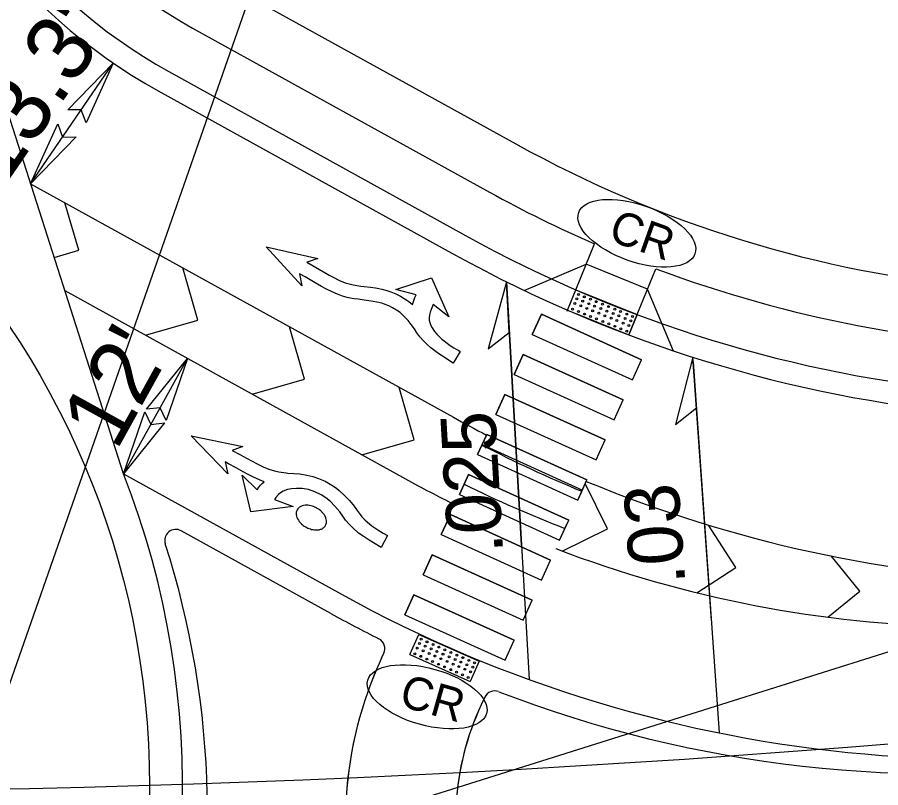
# Model space of a CAD drawing. Extents: x 2010838 to 2015151, y 441905 to 447792.
# Drawn here: x 2013251.3 to 2013329.7, y 444918.3 to 444988.3 of the extents above; entities that cross this region are included whole.
import ezdxf

# ---------------------------------------------------------------- set-up
doc = ezdxf.new("R2010")
doc.units = 0
for name, color, linetype in [('A-Wall-Abov', 7, 'Continuous'), ('A-Wall-Blow', 7, 'Continuous'), ('A-Wall-Comp', 7, 'Continuous'), ('C-Alignment Geometry', 7, 'Continuous'), ('C-CURB STOPS', 7, 'Continuous'), ('C-Grave Plots', 7, 'Continuous'), ('CLRD', 7, 'Continuous'), ('Default_10ft_LIDAR_Contou', 7, 'Continuous'), ('HATCH', 7, 'Continuous'), ('s-Existing Major', 7, 'Continuous'), ('S-Existing Minor', 7, 'Continuous'), ('S-overhead electric', 7, 'Continuous'), ('TEXT-LG', 7, 'Continuous'), ('TEXT-MED', 7, 'Continuous'), ('X4', 7, 'Continuous')]:
    doc.layers.add(name, color=color, linetype=linetype)

msp = doc.modelspace()

# ---------------------------------------------------------------- linework, layer by layer
at = {"layer": 'A-Wall-Abov'}
for points in [[(2013273.893, 444967.437), (2013278.566, 444966.374), (2013277.623, 444966.045), (2013277.588, 444966.033), (2013278.734, 444965.365), (2013279.321, 444965.031), (2013279.597, 444964.879), (2013280.083, 444964.616), (2013280.368, 444964.467), (2013280.557, 444964.377), (2013281.071, 444964.172), (2013281.419, 444964.066), (2013281.682, 444964.001), (2013281.973, 444963.944), (2013282.294, 444963.892), (2013282.492, 444963.866), (2013282.793, 444963.829), (2013283.38, 444963.785), (2013283.807, 444963.723), (2013284.116, 444963.664), (2013284.412, 444963.594), (2013284.847, 444963.47), (2013285.217, 444963.342), (2013285.656, 444963.16), (2013286.087, 444962.942), (2013286.426, 444962.741), (2013286.666, 444962.581), (2013286.839, 444962.455), (2013287.174, 444962.184), (2013287.232, 444962.371), (2013287.332, 444962.646), (2013287.402, 444962.819), (2013287.525, 444963.086), (2013285.656, 444963.558), (2013288.921, 444964.632), (2013290.493, 444961.071), (2013289.067, 444962.206), (2013288.989, 444962.041), (2013288.87, 444961.752), (2013288.78, 444961.488), (2013288.726, 444961.247), (2013288.704, 444960.992), (2013288.711, 444960.783), (2013288.784, 444960.461), (2013288.846, 444960.289), (2013288.963, 444960.068), (2013289.174, 444959.733), (2013289.393, 444959.5), (2013289.645, 444959.253), (2013289.862, 444959.057), (2013290.072, 444958.879), (2013290.327, 444958.679), (2013290.498, 444958.554), (2013290.694, 444958.418), (2013290.938, 444958.261), (2013291.142, 444958.138), (2013291.386, 444958.002), (2013291.505, 444957.939), (2013290.888, 444956.878), (2013290.45, 444957.146), (2013290.049, 444957.404), (2013289.684, 444957.649), (2013289.335, 444957.893), (2013289.104, 444958.062), (2013288.843, 444958.269), (2013288.518, 444958.557), (2013288.174, 444958.903), (2013287.859, 444959.266), (2013287.592, 444959.636), (2013287.356, 444959.996), (2013287.073, 444960.382), (2013286.777, 444960.741), (2013286.366, 444961.178), (2013286.061, 444961.461), (2013285.74, 444961.686), (2013285.365, 444961.908), (2013285.028, 444962.074), (2013284.707, 444962.206), (2013284.476, 444962.281), (2013284.112, 444962.366), (2013283.433, 444962.502), (2013282.804, 444962.603), (2013282.239, 444962.674), (2013281.887, 444962.712), (2013281.704, 444962.738), (2013281.241, 444962.832), (2013280.826, 444962.951), (2013280.356, 444963.127), (2013279.873, 444963.343), (2013279.37, 444963.593), (2013278.927, 444963.838), (2013278.345, 444964.174), (2013277.423, 444964.709), (2013276.928, 444964.99), (2013277.128, 444963.901)], [(2013267.078, 444950.245), (2013271.776, 444949.299), (2013270.807, 444948.934), (2013271.482, 444948.563), (2013272.149, 444948.197), (2013273.062, 444947.718), (2013273.616, 444947.443), (2013274.127, 444947.23), (2013274.65, 444947.071), (2013275.033, 444946.99), (2013275.704, 444946.896), (2013275.845, 444946.872), (2013276.948, 444946.799), (2013277.569, 444946.693), (2013278.141, 444946.549), (2013278.648, 444946.381), (2013279.244, 444946.125), (2013279.866, 444945.776), (2013280.282, 444945.486), (2013280.534, 444945.284), (2013281.005, 444944.84), (2013281.447, 444944.373), (2013281.87, 444943.871), (2013282.168, 444943.479), (2013282.42, 444943.119), (2013282.569, 444942.901), (2013282.893, 444942.581), (2013283.478, 444942.084), (2013284.023, 444941.698), (2013284.527, 444941.395), (2013284.922, 444941.19), (2013284.331, 444940.113), (2013283.791, 444940.428), (2013283.232, 444940.775), (2013282.696, 444941.129), (2013282.29, 444941.424), (2013281.793, 444941.849), (2013281.454, 444942.19), (2013281.11, 444942.587), (2013280.854, 444942.958), (2013280.573, 444943.342), (2013280.127, 444943.871), (2013279.719, 444944.285), (2013279.311, 444944.632), (2013278.876, 444944.902), (2013278.309, 444945.176), (2013277.747, 444945.364), (2013277.163, 444945.479), (2013276.638, 444945.481), (2013276.175, 444945.448), (2013275.819, 444945.376), (2013275.426, 444945.226), (2013275.186, 444945.074), (2013275.001, 444944.911), (2013274.761, 444944.645), (2013274.632, 444944.466), (2013276.338, 444943.832), (2013272.478, 444943.334), (2013271.708, 444946.691), (2013273.071, 444945.34), (2013273.218, 444945.576), (2013273.36, 444945.76), (2013273.522, 444945.933), (2013273.689, 444946.082), (2013273.336, 444946.225), (2013272.725, 444946.502), (2013272.263, 444946.739), (2013271.791, 444946.996), (2013271.15, 444947.346), (2013270.465, 444947.721), (2013270.172, 444947.881), (2013270.4, 444946.791)]]:
    msp.add_lwpolyline(points, close=True, dxfattribs=at)
for centre, radius, start, end in [((2013277.353, 444943.178), 0.742, 152.48491, 175.59848), ((2013277.239, 444943.238), 0.613, 151.25151, 152.48491), ((2013277.239, 444943.238), 0.613, 150.0181, 151.25151), ((2013277.35, 444943.173), 0.742, 126.90453, 150.0181), ((2013277.371, 444943.146), 0.777, 106.70357, 126.90453), ((2013277.549, 444942.55), 1.399, 83.97409, 106.70357), ((2013277.485, 444941.942), 2.01, 75.98922, 83.97409), ((2013277.463, 444941.851), 2.104, 63.29006, 75.98922), ((2013277.518, 444941.962), 1.98, 61.25151, 63.29006), ((2013277.518, 444941.962), 1.98, 59.21295, 61.25151), ((2013277.455, 444941.855), 2.104, 46.51379, 59.21295), ((2013277.387, 444943.176), 0.777, 175.59848, 195.79944), ((2013277.985, 444943.345), 1.399, 195.79944, 218.52892), ((2013277.519, 444941.923), 2.01, 38.52892, 46.51379), ((2013277.998, 444942.304), 1.399, 15.79944, 38.52892), ((2013278.596, 444942.473), 0.777, 355.59848, 15.79944), ((2013278.464, 444943.726), 2.01, 218.52892, 226.51379), ((2013278.528, 444943.794), 2.104, 226.51379, 239.21295), ((2013278.465, 444943.687), 1.98, 239.21295, 241.25151), ((2013278.465, 444943.687), 1.98, 241.25151, 243.29006), ((2013278.521, 444943.798), 2.104, 243.29006, 255.98922), ((2013278.613, 444942.503), 0.777, 286.70357, 306.90453), ((2013278.633, 444942.476), 0.742, 306.90453, 330.0181), ((2013278.745, 444942.411), 0.613, 330.0181, 331.25151), ((2013278.745, 444942.411), 0.613, 331.25151, 332.48491), ((2013278.631, 444942.471), 0.742, 332.48491, 355.59848), ((2013278.498, 444943.707), 2.01, 255.98922, 263.97409), ((2013278.434, 444943.099), 1.399, 263.97409, 286.70357)]:
    msp.add_arc(centre, radius, start, end, dxfattribs=at)
at = {"layer": 'A-Wall-Blow'}
for p, q in [((2013295.721, 444964.265), (2013297.793, 444928.095)), ((2013312.695, 444956.977), (2013315.07, 444923.243))]:
    msp.add_line(p, q, dxfattribs=at)
at = {"layer": 'A-Wall-Comp'}
for p, q in [((2013297.093, 444940.304), (2013295.721, 444964.265)), ((2013314.35, 444933.468), (2013312.664, 444957.409))]:
    msp.add_line(p, q, dxfattribs=at)
for points in [[(2013295.721, 444964.265), (2013294.067, 444958.16), (2013295.985, 444959.647)], [(2013312.664, 444957.409), (2013311.091, 444951.283), (2013312.989, 444952.795)]]:
    msp.add_lwpolyline(points, close=True, dxfattribs=at)
at = {"layer": 'C-Alignment Geometry'}
for p, q in [((2013252.47, 444973.181), (2013290.901, 444951.941)), ((2013256.846, 444967.123), (2013255.599, 444971.452)), ((2013254.618, 444966.481), (2013256.846, 444967.123)), ((2013267.666, 444960.784), (2013266.296, 444965.54)), ((2013255.585, 444963.462), (2013286.541, 444946.353)), ((2013262.91, 444959.414), (2013267.666, 444960.784)), ((2013277.372, 444955.42), (2013276.001, 444960.176)), ((2013272.615, 444954.049), (2013277.372, 444955.42)), ((2013287.342, 444949.909), (2013285.972, 444954.665)), ((2013282.586, 444948.539), (2013287.342, 444949.909)), ((2013304.915, 444941.803), (2013302.894, 444945.925)), ((2013316.577, 444938.28), (2013314.089, 444942.142)), ((2013300.79, 444939.78), (2013304.915, 444941.803)), ((2013327.832, 444936.126), (2013325.231, 444939.335)), ((2013313.027, 444935.993), (2013316.577, 444938.28)), ((2013324.924, 444933.77), (2013327.832, 444936.126))]:
    msp.add_line(p, q, dxfattribs=at)
for centre, radius, start, end in [((2013348.948, 445056.968), 120, 241.07113, 242.70119), ((2013338.783, 445040.877), 108, 241.07113, 243.76288), ((2013348.948, 445056.968), 120, 247.47739, 288.36141), ((2013338.783, 445040.877), 108, 249.07051, 288.90365)]:
    msp.add_arc(centre, radius, start, end, dxfattribs=at)
at = {"layer": 'C-CURB STOPS'}
for p, q in [((2013279.769, 444934.1), (2013266.154, 444941.625)), ((2013284.368, 444930.032), (2013284.582, 444930.49)), ((2013293.75, 444926.489), (2013293.431, 444925.805))]:
    msp.add_line(p, q, dxfattribs=at)
for centre, radius, start, end in [((2013265.67, 444940.75), 1, 61.07113, 197.7968), ((2013188.546, 444915.993), 80, 344.59886, 17.7968), ((2013338.783, 445040.877), 122, 241.07113, 243.38263), ((2013283.676, 444930.912), 1, 334.99432, 63.38263), ((2013316.088, 444915.237), 35, 154.99432, 197.96731), ((2013316.088, 444915.237), 35, 154.99432, 197.9163), ((2013294.656, 444926.067), 1, 68.87558, 154.99432), ((2013335.021, 445030.54), 111, 248.87558, 278.3239), ((2013316.088, 444915.237), 25, 154.99432, 197.96731), ((2013316.088, 444915.237), 25, 154.99432, 197.8959)]:
    msp.add_arc(centre, radius, start, end, dxfattribs=at)
at = {"layer": 'CLRD'}
for centre, radius, start, end in [((2013223.904, 446217.908), 1300, 266.626426, 322.205104), ((2013818.278, 444917.195), 630, 153.455725, 179.890795)]:
    msp.add_arc(centre, radius, start, end, dxfattribs=at)
at = {"layer": 'Default_10ft_LIDAR_Contou'}
msp.add_line((2013248.223, 444921.005), (2013289.464, 445039.081), dxfattribs=at)
at = {"layer": 'HATCH'}
for p, q in [((2013260.924, 444946.8), (2013240.662, 445010.031)), ((2013252.47, 444973.181), (2013259.983, 444984.145)), ((2013298.069, 444959.484), (2013298.896, 444961.305)), ((2013298.896, 444961.305), (2013298.069, 444959.484)), ((2013298.896, 444961.305), (2013308.001, 444957.17)), ((2013308.001, 444957.17), (2013298.896, 444961.305)), ((2013298.069, 444959.484), (2013307.174, 444955.349)), ((2013298.069, 444959.484), (2013307.174, 444955.349)), ((2013296.415, 444955.842), (2013297.242, 444957.663)), ((2013297.242, 444957.663), (2013296.415, 444955.842)), ((2013297.242, 444957.663), (2013306.347, 444953.528)), ((2013306.347, 444953.528), (2013297.242, 444957.663)), ((2013260.924, 444946.8), (2013266.728, 444957.303)), ((2013307.174, 444955.349), (2013308.001, 444957.17)), ((2013307.174, 444955.349), (2013308.001, 444957.17)), ((2013296.415, 444955.842), (2013305.52, 444951.707)), ((2013296.415, 444955.842), (2013305.52, 444951.707)), ((2013294.761, 444952.2), (2013295.588, 444954.021)), ((2013295.588, 444954.021), (2013294.761, 444952.2)), ((2013295.588, 444954.021), (2013304.693, 444949.886)), ((2013304.693, 444949.886), (2013295.588, 444954.021)), ((2013305.52, 444951.707), (2013306.347, 444953.528)), ((2013305.52, 444951.707), (2013306.347, 444953.528)), ((2013294.761, 444952.2), (2013303.866, 444948.065)), ((2013294.761, 444952.2), (2013303.866, 444948.065)), ((2013293.107, 444948.558), (2013293.934, 444950.379)), ((2013293.934, 444950.379), (2013293.5, 444949.424)), ((2013293.934, 444950.379), (2013303.038, 444946.244)), ((2013303.038, 444946.244), (2013293.934, 444950.379)), ((2013303.866, 444948.065), (2013304.693, 444949.886)), ((2013303.866, 444948.065), (2013304.693, 444949.886)), ((2013293.5, 444949.424), (2013293.107, 444948.558)), ((2013293.528, 444949.462), (2013302.633, 444945.327)), ((2013293.107, 444948.558), (2013302.211, 444944.423)), ((2013291.452, 444944.916), (2013292.279, 444946.737)), ((2013292.279, 444946.737), (2013291.877, 444945.852)), ((2013292.279, 444946.737), (2013301.384, 444942.602)), ((2013301.384, 444942.602), (2013292.279, 444946.737)), ((2013291.877, 444945.852), (2013291.452, 444944.916)), ((2013302.211, 444944.423), (2013303.038, 444946.244)), ((2013302.57, 444945.212), (2013303.038, 444946.244)), ((2013302.211, 444944.423), (2013302.57, 444945.212)), ((2013291.452, 444944.916), (2013300.557, 444940.781)), ((2013291.452, 444944.916), (2013300.557, 444940.781)), ((2013289.798, 444941.274), (2013290.625, 444943.095)), ((2013290.625, 444943.095), (2013289.798, 444941.274)), ((2013290.625, 444943.095), (2013299.73, 444938.96)), ((2013299.73, 444938.96), (2013290.625, 444943.095)), ((2013300.557, 444940.781), (2013301.384, 444942.602)), ((2013301.037, 444941.837), (2013301.384, 444942.602)), ((2013289.798, 444941.274), (2013298.903, 444937.139)), ((2013289.798, 444941.274), (2013298.903, 444937.139)), ((2013300.557, 444940.781), (2013301.037, 444941.837)), ((2013288.144, 444937.632), (2013288.971, 444939.453)), ((2013288.971, 444939.453), (2013288.144, 444937.632)), ((2013288.971, 444939.453), (2013298.076, 444935.318)), ((2013298.076, 444935.318), (2013288.971, 444939.453)), ((2013298.903, 444937.139), (2013299.73, 444938.96)), ((2013298.903, 444937.139), (2013299.73, 444938.96)), ((2013288.144, 444937.632), (2013297.249, 444933.497)), ((2013288.144, 444937.632), (2013297.249, 444933.497)), ((2013286.49, 444933.99), (2013287.317, 444935.811)), ((2013287.317, 444935.811), (2013286.49, 444933.99)), ((2013287.317, 444935.811), (2013296.422, 444931.676)), ((2013296.422, 444931.676), (2013287.317, 444935.811)), ((2013297.249, 444933.497), (2013298.076, 444935.318)), ((2013297.249, 444933.497), (2013298.076, 444935.318)), ((2013286.49, 444933.99), (2013295.595, 444929.855)), ((2013286.49, 444933.99), (2013295.595, 444929.855)), ((2013295.595, 444929.855), (2013296.422, 444931.676)), ((2013295.595, 444929.855), (2013296.422, 444931.676))]:
    msp.add_line(p, q, dxfattribs=at)
msp.add_circle((2013188.28, 444918.396), 75, dxfattribs=at)
for centre, radius, start, end in [((2013348.527, 445056.064), 120, 242.70597, 247.48217), ((2013348.527, 445056.064), 120, 242.70597, 247.48217), ((2013342.978, 445049.99), 116, 243.86295, 248.80421), ((2013342.978, 445049.99), 116, 243.86295, 248.80421)]:
    msp.add_arc(centre, radius, start, end, dxfattribs=at)
at = {"layer": 's-Existing Major'}
for points in [[(2013255.845, 444979.889), (2013259.983, 444984.145), (2013257.516, 444978.704), (2013257.08, 444979.909)], [(2013256.608, 444977.438), (2013252.47, 444973.181), (2013254.938, 444978.622), (2013255.373, 444977.417)], [(2013263.017, 444952.67), (2013266.728, 444957.303), (2013264.793, 444951.652), (2013264.245, 444952.809)], [(2013264.635, 444951.433), (2013260.924, 444946.8), (2013262.859, 444952.452), (2013263.408, 444951.295)]]:
    msp.add_lwpolyline(points, close=True, dxfattribs=at)
at = {"layer": 'S-Existing Minor'}
for p, q in [((2013252.47, 444973.181), (2013259.983, 444984.145)), ((2013260.924, 444946.8), (2013266.728, 444957.303)), ((2012728.005, 444741.112), (2013407.247, 444954.802))]:
    msp.add_line(p, q, dxfattribs=at)
at = {"layer": 'S-overhead electric'}
for p, q in [((2013264.059, 444981.63), (2013291.026, 444966.726)), ((2013260.924, 444946.8), (2013280.736, 444935.85))]:
    msp.add_line(p, q, dxfattribs=at)
for centre, radius, start, end in [((2013288.245, 445025.391), 50, 190.65487, 241.07113), ((2013349.072, 445071.752), 120, 241.07113, 288.18835), ((2013188.28, 444918.396), 78, 333.4342, 21.35599), ((2013338.783, 445040.877), 120, 241.07113, 288.90365), ((2013488.978, 444297.364), 630, 97.858337, 111.50371)]:
    msp.add_arc(centre, radius, start, end, dxfattribs=at)
at = {"layer": 'TEXT-LG'}
for p, q in [((2013269.621, 444991.695), (2013296.588, 444976.791)), ((2013267.203, 444987.319), (2013294.17, 444972.415)), ((2013301.253, 444961.598), (2013303.727, 444967.704)), ((2013297.35, 444963.471), (2013302.977, 444965.852)), ((2013308.537, 444963.599), (2013302.977, 444965.852)), ((2013306.846, 444959.427), (2013309.289, 444965.453)), ((2013301.286, 444961.68), (2013302.037, 444963.534)), ((2013302.037, 444963.534), (2013307.598, 444961.281)), ((2013310.921, 444957.967), (2013308.537, 444963.599)), ((2013301.286, 444961.68), (2013306.846, 444959.427)), ((2013307.598, 444961.281), (2013306.846, 444959.427)), ((2013286.947, 444930.365), (2013287.756, 444932.194)), ((2013287.756, 444932.194), (2013293.242, 444929.767)), ((2013286.946, 444930.366), (2013292.433, 444927.938)), ((2013293.242, 444929.767), (2013292.433, 444927.938))]:
    msp.add_line(p, q, dxfattribs=at)
for centre in [(2013302.273, 444963.116), (2013301.943, 444962.29), (2013302.121, 444962.714), (2013302.653, 444962.497), (2013302.804, 444962.899), (2013303.208, 444962.27), (2013303.36, 444962.672), (2013303.891, 444962.455), (2013304.447, 444962.228), (2013301.742, 444961.774), (2013302.274, 444961.557), (2013302.474, 444962.073), (2013303.029, 444961.846), (2013303.561, 444961.629), (2013303.739, 444962.053), (2013304.116, 444961.402), (2013304.295, 444961.826), (2013304.86, 444961.6), (2013305.012, 444962.002), (2013305.567, 444961.775), (2013306.099, 444961.558), (2013302.829, 444961.33), (2013303.361, 444961.113), (2013303.916, 444960.886), (2013304.481, 444960.66), (2013304.681, 444961.176), (2013305.237, 444960.949), (2013305.415, 444961.373), (2013305.768, 444960.732), (2013305.947, 444961.156), (2013306.502, 444960.929), (2013306.654, 444961.331), (2013307.034, 444960.712), (2013307.185, 444961.114), (2013305.037, 444960.433), (2013305.568, 444960.215), (2013306.123, 444959.988), (2013306.324, 444960.505), (2013306.855, 444960.288), (2013306.655, 444959.771), (2013287.978, 444931.77), (2013287.622, 444930.955), (2013287.814, 444931.373), (2013288.338, 444931.139), (2013288.503, 444931.536), (2013288.886, 444930.895), (2013289.051, 444931.291), (2013289.575, 444931.058), (2013290.123, 444930.813), (2013287.406, 444930.445), (2013287.93, 444930.211), (2013288.146, 444930.721), (2013288.694, 444930.476), (2013289.219, 444930.242), (2013289.41, 444930.661), (2013289.767, 444929.998), (2013289.958, 444930.416), (2013290.516, 444930.173), (2013290.681, 444930.57), (2013291.229, 444930.325), (2013291.753, 444930.091), (2013288.478, 444929.966), (2013289.002, 444929.733), (2013289.55, 444929.488), (2013290.108, 444929.245), (2013290.324, 444929.754), (2013290.872, 444929.51), (2013291.064, 444929.928), (2013291.397, 444929.276), (2013291.589, 444929.694), (2013292.136, 444929.45), (2013292.301, 444929.847), (2013292.661, 444929.216), (2013292.825, 444929.613), (2013290.656, 444929), (2013291.18, 444928.766), (2013291.728, 444928.522), (2013291.945, 444929.032), (2013292.469, 444928.798), (2013292.252, 444928.288)]:
    msp.add_circle(centre, 0.0869, dxfattribs=at)
for centre, radius, start, end in [((2013288.245, 445025.391), 43.5, 190.65487, 241.07113), ((2013349.072, 445071.752), 108.5, 241.07113, 288.18835), ((2013349.072, 445071.752), 113.5, 241.07113, 246.45199), ((2013349.072, 445071.752), 113.5, 249.48094, 288.18835)]:
    msp.add_arc(centre, radius, start, end, dxfattribs=at)
at = {"layer": 'TEXT-MED'}
msp.add_line((2013265.026, 444983.381), (2013291.993, 444968.476), dxfattribs=at)
for centre, radius, start, end in [((2013288.245, 445025.391), 48, 190.65487, 241.07113), ((2013349.072, 445071.752), 118, 241.07113, 288.18835)]:
    msp.add_arc(centre, radius, start, end, dxfattribs=at)
at = {"layer": 'X4'}
for centre, major_axis in [((2013307.577, 444968.677), (5.284, -1.876)), ((2013288.516, 444926.532), (5.398, -1.516))]:
    msp.add_ellipse(centre, major_axis=major_axis, ratio=0.462467, dxfattribs=at)

# ---------------------------------------------------------------- texts
at = {"layer": 'A-Wall-Blow'}
for s, rotation, p in [('.025', 93.27869, (2013295.431, 444939.614)), ('.03', 94.02794, (2013311.995, 444936.805))]:
    msp.add_text(s, height=5, rotation=rotation, dxfattribs=at).set_placement(p)
at = {"layer": 'C-Grave Plots'}
for s, rotation, p in [("13.3'", 55.58098, (2013250.005, 444972.784)), ("12'", 61.07113, (2013260.26, 444948.796))]:
    msp.add_text(s, height=6, rotation=rotation, dxfattribs=at).set_placement(p)
at = {"layer": 'X4'}
for rotation, p in [(340.44789, (2013304.862, 444968.074)), (344.31712, (2013285.848, 444925.747))]:
    msp.add_text('CR', height=3, rotation=rotation, dxfattribs=at).set_placement(p)

doc.saveas('drawing.dxf')
